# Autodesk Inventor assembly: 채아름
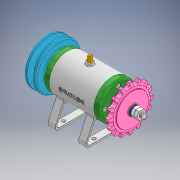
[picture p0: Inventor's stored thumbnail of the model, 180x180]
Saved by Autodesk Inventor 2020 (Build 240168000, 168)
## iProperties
Created: 2021-12
Part Number: 채아름
Document SubType Name: Assembly
Designer: Windows7
Author: Windows7
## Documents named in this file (16)
- C:\Users\Windows7\Desktop\711206V1033\답안조립품.iam
- C:\Users\Windows7\Desktop\711206V1033\본체.ipt
- C:\Users\Windows7\Desktop\711206V1033\V벨트풀리.ipt
- C:\Users\Windows7\Desktop\711206V1033\너트 M8.ipt
- C:\Users\Windows7\Desktop\711206V1033\니플 M6 x 0.75.ipt
- C:\Users\Windows7\Desktop\711206V1033\베어링 6002.ipt
- C:\Users\Windows7\Desktop\711206V1033\볼트 M4 x 12.ipt
- C:\Users\Windows7\Desktop\711206V1033\볼트 M6 x 8.ipt
- C:\Users\Windows7\Desktop\711206V1033\스프로킷.ipt
- C:\Users\Windows7\Desktop\711206V1033\스프링와셔 8.ipt
- C:\Users\Windows7\Desktop\711206V1033\오일 실 15 x 25 x 7.ipt
- C:\Users\Windows7\Desktop\711206V1033\와셔 6 x 11.5.ipt
- C:\Users\Windows7\Desktop\711206V1033\와셔 8 x 17.ipt
- C:\Users\Windows7\Desktop\711206V1033\축.ipt
- C:\Users\Windows7\Desktop\711206V1033\커버.ipt
- C:\Users\Windows7\Desktop\711206V1033\키 3 x 3.ipt
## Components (11 placed, 3 different names)
1. V벨트풀리:1
2. KS B 2023 6002 - 15 x 32 x 9:1
3. KS B 2023 6002 - 15 x 32 x 9:2
4. ISO 4762 M4 x 12:1 — 각도:4
5. ISO 4762 M4 x 12:2
6. ISO 4762 M4 x 12:3
7. ISO 4762 M4 x 12:4
8. ISO 4762 M4 x 12:5
9. ISO 4762 M4 x 12:6 — 각도:2, 각도:5
10. ISO 4762 M4 x 12:7
11. ISO 4762 M4 x 12:8
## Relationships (3: Angle 3)
- 각도:2 [Angle]: ISO 4762 M4 x 12:6
- 각도:4 [Angle]: ISO 4762 M4 x 12:1
- 각도:5 [Angle]: ISO 4762 M4 x 12:6
